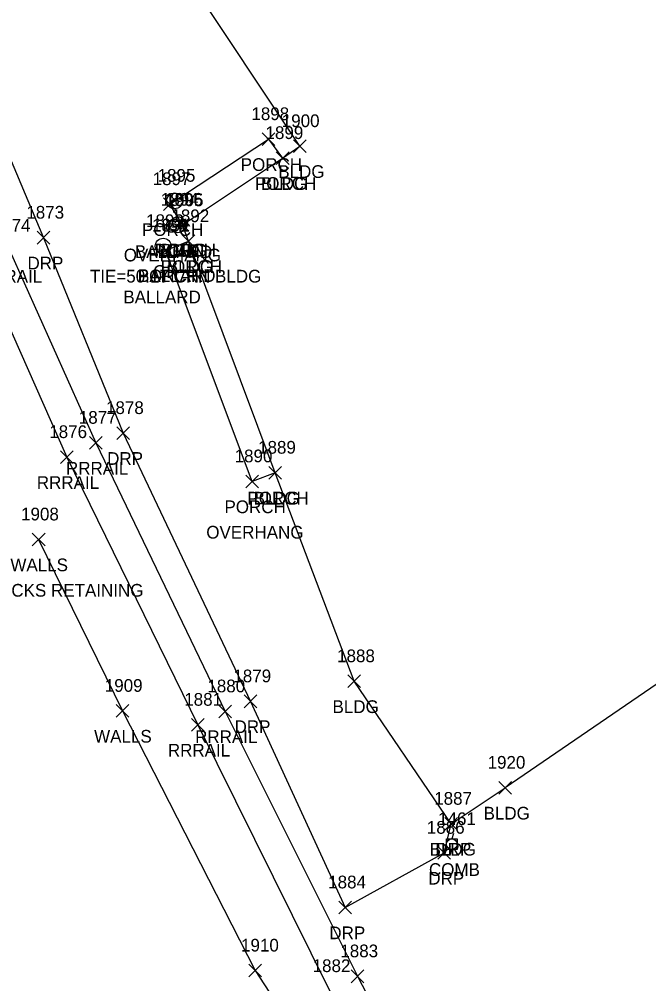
# Model space of a CAD drawing. Extents: x 1635588 to 1637550, y 621583 to 623638.
# Drawn here: x 1636661.5 to 1636760.5, y 622323.2 to 622475 of the extents above; entities that cross this region are included whole.
import ezdxf

# ---------------------------------------------------------------- set-up
doc = ezdxf.new("R2010")
doc.units = 0
for name, color, linetype in [('C_A', 7, 'Continuous'), ('C_C', 7, 'Continuous'), ('C_I', 7, 'Continuous'), ('CBP', 7, 'Continuous'), ('L_A', 7, 'Continuous'), ('L_C', 7, 'Continuous'), ('L_I', 7, 'Continuous'), ('L_TIC', 7, 'Continuous'), ('LBC', 7, 'Continuous'), ('LBF', 7, 'Continuous'), ('LWS', 7, 'Continuous'), ('R_A', 7, 'Continuous'), ('R_C', 7, 'Continuous'), ('R_I', 7, 'Continuous'), ('R_TIC', 7, 'Continuous'), ('RDP', 7, 'Continuous'), ('RGP', 7, 'Continuous'), ('RR', 7, 'Continuous'), ('U_A', 7, 'Continuous'), ('U_I', 7, 'Continuous'), ('UP', 7, 'Continuous')]:
    doc.layers.add(name, color=color, linetype=linetype)

msp = doc.modelspace()

# ---------------------------------------------------------------- linework, layer by layer
at = {"layer": 'CBP'}
for radius in [0.625, 0.0833]:
    msp.add_circle((1636687.28, 622442.56), radius, dxfattribs=at)
at = {"layer": 'L_TIC'}
for points in [[(1636699.69, 622455.12), (1636701.69, 622457.12)], [(1636701.69, 622455.12), (1636699.69, 622457.12)], [(1636704.64, 622454.02), (1636706.64, 622456.02)], [(1636706.64, 622454.02), (1636704.64, 622456.02)], [(1636701.92, 622452.14), (1636703.92, 622454.14)], [(1636703.92, 622452.14), (1636701.92, 622454.14)], [(1636701.92, 622452.14), (1636703.92, 622454.14)], [(1636703.92, 622452.14), (1636701.92, 622454.14)], [(1636684.15, 622444.89), (1636686.15, 622446.89)], [(1636686.15, 622444.89), (1636684.15, 622446.89)], [(1636686.15, 622441.65), (1636688.15, 622443.65)], [(1636688.15, 622441.65), (1636686.15, 622443.65)], [(1636686.15, 622441.65), (1636688.15, 622443.65)], [(1636688.15, 622441.65), (1636686.15, 622443.65)], [(1636687.1, 622439.06), (1636689.1, 622441.06)], [(1636689.1, 622439.06), (1636687.1, 622441.06)], [(1636687.1, 622439.06), (1636689.1, 622441.06)], [(1636689.1, 622439.06), (1636687.1, 622441.06)], [(1636683.48, 622437.59), (1636685.48, 622439.59)], [(1636685.48, 622437.59), (1636683.48, 622439.59)], [(1636700.75, 622402.63), (1636702.75, 622404.63)], [(1636702.75, 622402.63), (1636700.75, 622404.63)], [(1636700.75, 622402.63), (1636702.75, 622404.63)], [(1636702.75, 622402.63), (1636700.75, 622404.63)], [(1636697.14, 622401.27), (1636699.14, 622403.27)], [(1636699.14, 622401.27), (1636697.14, 622403.27)], [(1636663.51, 622392.13), (1636665.51, 622394.13)], [(1636665.51, 622392.13), (1636663.51, 622394.13)], [(1636713.18, 622369.82), (1636715.18, 622371.82)], [(1636715.18, 622369.82), (1636713.18, 622371.82)], [(1636676.7, 622365.16), (1636678.7, 622367.16)], [(1636678.7, 622365.16), (1636676.7, 622367.16)], [(1636736.96, 622353.06), (1636738.96, 622355.06)], [(1636738.96, 622353.06), (1636736.96, 622355.06)], [(1636728.47, 622347.39), (1636730.47, 622349.39)], [(1636730.47, 622347.39), (1636728.47, 622349.39)], [(1636728.47, 622347.39), (1636730.47, 622349.39)], [(1636730.47, 622347.39), (1636728.47, 622349.39)], [(1636697.58, 622324.29), (1636699.58, 622326.29)], [(1636699.58, 622324.29), (1636697.58, 622326.29)]]:
    msp.add_lwpolyline(points, dxfattribs=at)
at = {"layer": 'LBC'}
for points in [[(1636729.47, 622348.39), (1636714.18, 622370.82), (1636701.75, 622403.63), (1636688.1, 622440.06), (1636687.15, 622442.65), (1636702.92, 622453.14), (1636705.64, 622455.02), (1636670.45, 622507.84)], [(1636801.89, 622397.79), (1636737.96, 622354.06)], [(1636729.47, 622348.39), (1636737.96, 622354.06)]]:
    msp.add_lwpolyline(points, dxfattribs=at)
at = {"layer": 'LBF'}
for points in [[(1636687.15, 622442.65), (1636685.15, 622445.89), (1636700.69, 622456.12), (1636702.92, 622453.14)], [(1636701.75, 622403.63), (1636698.14, 622402.27), (1636684.48, 622438.59), (1636688.1, 622440.06)]]:
    msp.add_lwpolyline(points, dxfattribs=at)
at = {"layer": 'LWS'}
msp.add_lwpolyline([(1636664.51, 622393.13), (1636677.7, 622366.16), (1636698.58, 622325.29), (1636705.24, 622315.08)], dxfattribs=at)
at = {"layer": 'R_TIC'}
for points in [[(1636664.26, 622439.62), (1636666.26, 622441.62)], [(1636666.26, 622439.62), (1636664.26, 622441.62)], [(1636676.8, 622408.87), (1636678.8, 622410.87)], [(1636678.8, 622408.87), (1636676.8, 622410.87)], [(1636672.52, 622407.34), (1636674.52, 622409.34)], [(1636674.52, 622407.34), (1636672.52, 622409.34)], [(1636667.93, 622405.09), (1636669.93, 622407.09)], [(1636669.93, 622405.09), (1636667.93, 622407.09)], [(1636696.86, 622366.66), (1636698.86, 622368.66)], [(1636698.86, 622366.66), (1636696.86, 622368.66)], [(1636692.85, 622365.08), (1636694.85, 622367.08)], [(1636694.85, 622365.08), (1636692.85, 622367.08)], [(1636688.56, 622362.97), (1636690.56, 622364.97)], [(1636690.56, 622362.97), (1636688.56, 622364.97)], [(1636728.47, 622347.39), (1636730.47, 622349.39)], [(1636730.47, 622347.39), (1636728.47, 622349.39)], [(1636727.36, 622342.83), (1636729.36, 622344.83)], [(1636729.36, 622342.83), (1636727.36, 622344.83)], [(1636711.78, 622334.23), (1636713.78, 622336.23)], [(1636713.78, 622334.23), (1636711.78, 622336.23)], [(1636713.7, 622323.39), (1636715.7, 622325.39)], [(1636715.7, 622323.39), (1636713.7, 622325.39)]]:
    msp.add_lwpolyline(points, dxfattribs=at)
at = {"layer": 'RDP'}
msp.add_lwpolyline([(1636646.02, 622588.86), (1636648.84, 622578.89), (1636636.11, 622574.95), (1636645.72, 622538.78), (1636652.05, 622538.81), (1636655.67, 622532), (1636635.76, 622522.73), (1636650.96, 622474.58), (1636665.26, 622440.62), (1636677.8, 622409.87), (1636697.86, 622367.66), (1636712.78, 622335.23), (1636728.36, 622343.83), (1636729.47, 622348.39)], dxfattribs=at)
at = {"layer": 'RGP'}
for p, q in [((1636685.92, 622446.42), (1636685.92, 622446.42)), ((1636686.42, 622442.65), (1636686.42, 622442.65)), ((1636684.11, 622439.29), (1636684.11, 622439.29))]:
    msp.add_line(p, q, dxfattribs=at)
for centre, radius in [((1636685.92, 622446.42), 1.25), ((1636685.92, 622446.42), 0.0833), ((1636686.42, 622442.65), 1.25), ((1636686.42, 622442.65), 0.0833), ((1636684.11, 622439.29), 1.25), ((1636684.11, 622439.29), 0.0833)]:
    msp.add_circle(centre, radius, dxfattribs=at)
at = {"layer": 'RR'}
for points in [[(1636595.36, 622644.51), (1636608.64, 622596.11), (1636625.13, 622537.69), (1636636.8, 622500.24), (1636648.02, 622468.59), (1636659.97, 622438.55), (1636673.52, 622408.34), (1636693.85, 622366.08), (1636714.7, 622324.39), (1636733.88, 622287.48), (1636747.97, 622261.4), (1636765.42, 622232.02), (1636782.99, 622205.69), (1636804, 622177.32), (1636821.45, 622155.32), (1636839.4, 622134.64), (1636866.41, 622104.91), (1636933.01, 622032.15), (1636992.12, 621967.88), (1637026.25, 621930.62), (1637051.37, 621903.17)], [(1636590.62, 622643.06), (1636603.96, 622594.72), (1636620.27, 622536.36), (1636632.07, 622498.45), (1636643.29, 622466.78), (1636655.39, 622436.56), (1636668.93, 622406.09), (1636689.56, 622363.97), (1636710.33, 622322.06), (1636729.55, 622284.99), (1636743.57, 622259.26), (1636761.55, 622228.91), (1636778.55, 622203.2), (1636800.49, 622173.78), (1636817.8, 622151.9), (1636836.04, 622130.9), (1636862.72, 622101.67), (1636929.58, 622028.72), (1636988.41, 621964.46), (1637027.08, 621922.66), (1637047.82, 621899.75)]]:
    msp.add_lwpolyline(points, dxfattribs=at)
at = {"layer": 'UP'}
for p, q in [((1636728.73, 622344.36), (1636728.73, 622346.03)), ((1636728.73, 622346.03), (1636730.4, 622346.03)), ((1636729.81, 622346.86), (1636729.56, 622346.03)), ((1636730.4, 622346.03), (1636730.4, 622344.36)), ((1636730.4, 622344.36), (1636728.73, 622344.36)), ((1636729.31, 622343.53), (1636729.56, 622344.36)), ((1636729.56, 622345.19), (1636729.56, 622345.19))]:
    msp.add_line(p, q, dxfattribs=at)
msp.add_circle((1636729.56, 622345.19), 0.833, dxfattribs=at)

# ---------------------------------------------------------------- texts
at = {"layer": 'C_A'}
msp.add_text('TIE', height=2, dxfattribs=at).set_placement((1636685.36, 622437.56))
at = {"layer": 'C_C'}
msp.add_text('TIE=50.17 CRN BLDG', height=2, dxfattribs=at).set_placement((1636672.58, 622433.56))
at = {"layer": 'C_I'}
msp.add_text('1905', height=2, dxfattribs=at).set_placement((1636684.51, 622445.56))
at = {"layer": 'L_A'}
for s, p in [('PORCH', (1636696.32, 622451.12)), ('BLDG', (1636702.23, 622450.02)), ('PORCH', (1636698.55, 622448.14)), ('BLDG', (1636699.51, 622448.14)), ('PORCH', (1636680.77, 622440.89)), ('PORCH', (1636682.77, 622437.65)), ('BLDG', (1636683.74, 622437.65)), ('PORCH', (1636683.72, 622435.06)), ('BLDG', (1636684.69, 622435.06)), ('PORCH', (1636680.11, 622433.59)), ('PORCH', (1636697.37, 622398.63)), ('BLDG', (1636698.34, 622398.63)), ('PORCH', (1636693.76, 622397.27)), ('WALLS', (1636660.06, 622388.13)), ('BLDG', (1636710.77, 622365.82)), ('WALLS', (1636673.24, 622361.16)), ('BLDG', (1636734.55, 622349.06)), ('BLDG', (1636726.06, 622343.39)), ('BLDG', (1636726.06, 622343.39))]:
    msp.add_text(s, height=2, dxfattribs=at).set_placement(p)
at = {"layer": 'L_C'}
for s, p in [('OVERHANG', (1636677.91, 622436.89)), ('OVERHANG', (1636690.9, 622393.27)), ('CONC BLOCKS RETAINING', (1636646.24, 622384.13))]:
    msp.add_text(s, height=2, dxfattribs=at).set_placement(p)
at = {"layer": 'L_I'}
for s, p in [('1898', (1636698, 622459.12)), ('1900', (1636702.78, 622458.02)), ('1899', (1636700.22, 622456.14)), ('1899', (1636700.22, 622456.14)), ('1897', (1636682.46, 622448.89)), ('1896', (1636684.4, 622445.65)), ('1896', (1636684.4, 622445.65)), ('1892', (1636685.41, 622443.06)), ('1892', (1636685.41, 622443.06)), ('1891', (1636682.36, 622441.59)), ('1889', (1636699.05, 622406.63)), ('1889', (1636699.05, 622406.63)), ('1890', (1636695.36, 622405.27)), ('1908', (1636661.74, 622396.13)), ('1888', (1636711.49, 622373.82)), ('1909', (1636674.92, 622369.16)), ('1920', (1636735.18, 622357.06)), ('1887', (1636726.78, 622351.39)), ('1887', (1636726.78, 622351.39)), ('1910', (1636696.37, 622328.29))]:
    msp.add_text(s, height=2, dxfattribs=at).set_placement(p)
at = {"layer": 'R_A'}
for s, p in [('GP', (1636684.35, 622441.42)), ('GP', (1636684.85, 622437.65)), ('DRP', (1636662.75, 622435.62)), ('RRRAIL', (1636655.26, 622433.55)), ('GP', (1636682.54, 622434.29)), ('DRP', (1636675.29, 622404.87)), ('RRRAIL', (1636668.81, 622403.34)), ('RRRAIL', (1636664.22, 622401.09)), ('DRP', (1636695.35, 622362.66)), ('RRRAIL', (1636689.14, 622361.08)), ('RRRAIL', (1636684.85, 622358.97)), ('DRP', (1636726.96, 622343.39)), ('DRP', (1636725.85, 622338.83)), ('DRP', (1636710.27, 622330.23))]:
    msp.add_text(s, height=2, dxfattribs=at).set_placement(p)
at = {"layer": 'R_C'}
for p in [(1636679.66, 622437.42), (1636680.16, 622433.65), (1636677.85, 622430.29)]:
    msp.add_text('BALLARD', height=2, dxfattribs=at).set_placement(p)
at = {"layer": 'R_I'}
for s, p in [('1895', (1636683.23, 622449.42)), ('1894', (1636683.73, 622445.65)), ('1873', (1636662.57, 622443.62)), ('1874', (1636657.28, 622441.55)), ('1893', (1636681.42, 622442.29)), ('1878', (1636675.11, 622412.87)), ('1877', (1636670.83, 622411.34)), ('1876', (1636666.18, 622409.09)), ('1879', (1636695.16, 622370.66)), ('1880', (1636691.07, 622369.08)), ('1881', (1636687.43, 622366.97)), ('1887', (1636726.78, 622351.39)), ('1886', (1636725.62, 622346.83)), ('1884', (1636710.09, 622338.23)), ('1883', (1636712, 622327.39)), ('1882', (1636707.64, 622325.06))]:
    msp.add_text(s, height=2, dxfattribs=at).set_placement(p)
at = {"layer": 'U_A'}
msp.add_text('COMB', height=2, dxfattribs=at).set_placement((1636725.95, 622340.19))
at = {"layer": 'U_I'}
msp.add_text('1461', height=2, dxfattribs=at).set_placement((1636727.39, 622348.19))

doc.saveas('drawing.dxf')
